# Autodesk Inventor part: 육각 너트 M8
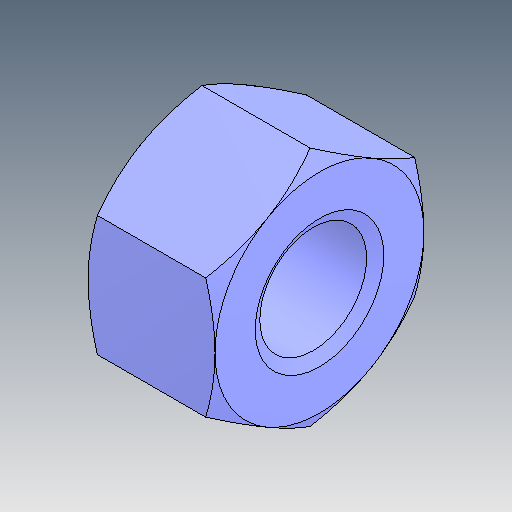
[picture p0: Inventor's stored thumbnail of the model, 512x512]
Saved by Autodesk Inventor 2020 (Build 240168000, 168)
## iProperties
Created: 2024-11
Part Number: 육각 너트 M8
Material: 강철, 연강
Description: 6각 너트 및 6각 가는 너트
Document SubType Name: Modeling
Designer: shin
Density: 7.85 g/cm^3
Appearance: 기본값
Author: jhkim
Sending System: Autodesk Inventor 2025
Preprocessor: ST-DEVELOPER v20
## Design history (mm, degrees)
feature "Solid1"
node "솔리드1"
